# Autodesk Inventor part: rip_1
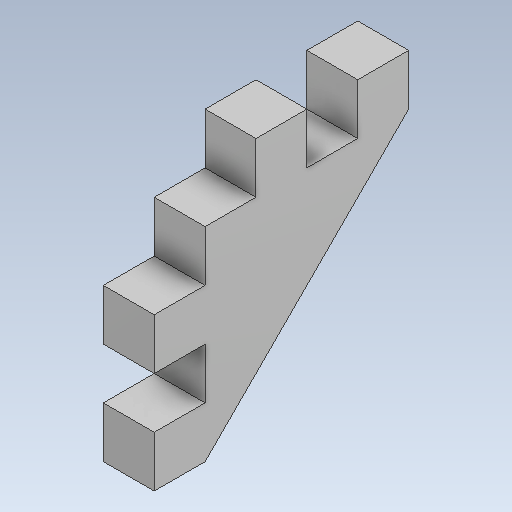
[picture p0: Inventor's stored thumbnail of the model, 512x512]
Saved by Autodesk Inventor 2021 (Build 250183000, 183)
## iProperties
Created: 2026-10
Part Number: rip_1
Material: Generic
Document SubType Name: Modeling
Designer: hp
Density: 1 g/cm^3
Appearance: Default
Author: hp
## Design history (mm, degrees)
feature "Body1"
body "Solid1"
